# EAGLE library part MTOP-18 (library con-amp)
AMP connector
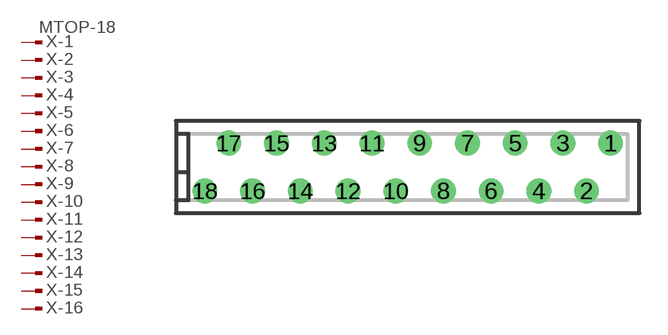
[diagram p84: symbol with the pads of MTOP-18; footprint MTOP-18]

Designator prefix X; gates -1=PIN-MV -2=PIN-M -3=PIN-M -4=PIN-M -5=PIN-M -6=PIN-M -7=PIN-M -8=PIN-M -9=PIN-M -10=PIN-M -11=PIN-M -12=PIN-M -13=PIN-M -14=PIN-M -15=PIN-M -16=PIN-M -17=PIN-M -18=PIN-M

## MTOP-18 (OC_FARNELL: unknown; OC_NEWARK: unknown)  [MTOP-18]
1  -1:1  pas
2  -2:1  pas
3  -3:1  pas
4  -4:1  pas
5  -5:1  pas
6  -6:1  pas
7  -7:1  pas
8  -8:1  pas
9  -9:1  pas
10  -10:1  pas
11  -11:1  pas
12  -12:1  pas
13  -13:1  pas
14  -14:1  pas
15  -15:1  pas
16  -16:1  pas
17  -17:1  pas
18  -18:1  pas

## Footprint MTOP-18 (pad centres in mm)
AMP connector
drill 0.813 round: 1 10.795,1.27; 2 9.525,-1.27; 3 8.255,1.27; 4 6.985,-1.27; 5 5.715,1.27; 6 4.445,-1.27; 7 3.175,1.27; 8 1.905,-1.27; 9 0.635,1.27; 10 -0.635,-1.27; 11 -1.905,1.27; 12 -3.175,-1.27; 13 -4.445,1.27; 14 -5.715,-1.27; 15 -6.985,1.27; 16 -8.255,-1.27; 17 -9.525,1.27; 18 -10.795,-1.27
